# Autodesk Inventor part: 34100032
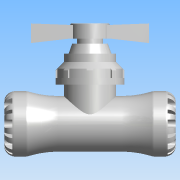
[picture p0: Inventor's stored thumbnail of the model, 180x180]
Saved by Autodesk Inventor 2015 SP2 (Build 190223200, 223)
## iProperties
Created: 2016-12
Part Number: 34100032
Material: PVC-Piping
Description: Plasson COMPRESSION STOPTAP 32 SERIES 1
Document SubType Name: Modeling
Designer: KIM
Mass: 61.7504 g
Surface Area: 140.097 cm^2
Volume: 44.1074 cm^3
Density: 1.4 g/cm^3
Appearance: Smooth - White
Author: KIM
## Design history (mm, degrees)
derived "03410.ipt"
feature "Solid1::03410.ipt"
feature "Solid2::03410.ipt"
tag "TaggingFeature1"
body "Solid1"
other parameters: "d1" = 20.16, "d2" = 32, "d4" = 58, "d6" = 48, "d8" = 49.3, "d13" = 7.2, "d14" = 7.2, "d15" = 0, "d17" = 360 deg, "d19" = 8 deg, "d20" = 0.64, "d21" = 0.64, "d22" = 8 deg, "d24" = 0, "d26" = 360 deg, "d33" = 5.8, "d35" = 4, "d65" = 0.58, "d69" = 152, "d71" = 32, "d72" = 58, "d74" = 20.16, "d75" = 76, "d76" = 4, "d77" = 48, "d80" = 7.2, "d82" = 7.2, "d83" = 0, "d85" = 360 deg, "d92" = 0, "d94" = 360 deg, "d96" = 89, "d97" = 58, "d98" = 46.4, "d99" = 34.8, "d100" = 135 deg, "d101" = 23.2, "d102" = 70 deg, "d103" = 48.95, "d104" = 71.2, "d105" = 62.3, "d107" = 75.65, "d108" = 104.4, "d110" = 12.015, "d111" = 4.005, "d112" = 17.4, "d113" = 0, "d114" = 60.9, "d115" = 5.8, "d116" = 0, "d117" = 5.8, "d119" = 0, "d121" = 360 deg, "d126" = 0.64, "d127" = 0.64, "d128" = 8 deg, "d129" = 8 deg, "d130" = 0.58, "d132" = 0, "d_" = 32, "E_" = 58, "H_" = 152, "l_" = 48, "A_" = 89, "l_1" = 48, "E_1" = 58, "d9" = 9, "d11" = 58, "d78" = 58, "d81" = 9, "d109" = 13.35
